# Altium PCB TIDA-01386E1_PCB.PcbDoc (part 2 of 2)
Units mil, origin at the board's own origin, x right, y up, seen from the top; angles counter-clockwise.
Board outline 3000 x 700 mil, 4 copper layers (Top Layer, Signal Layer 1, Signal Layer 2, Bottom Layer), stack 90.316 mil thick; 67 components, 41 nets, 217 pads, 102 vias.
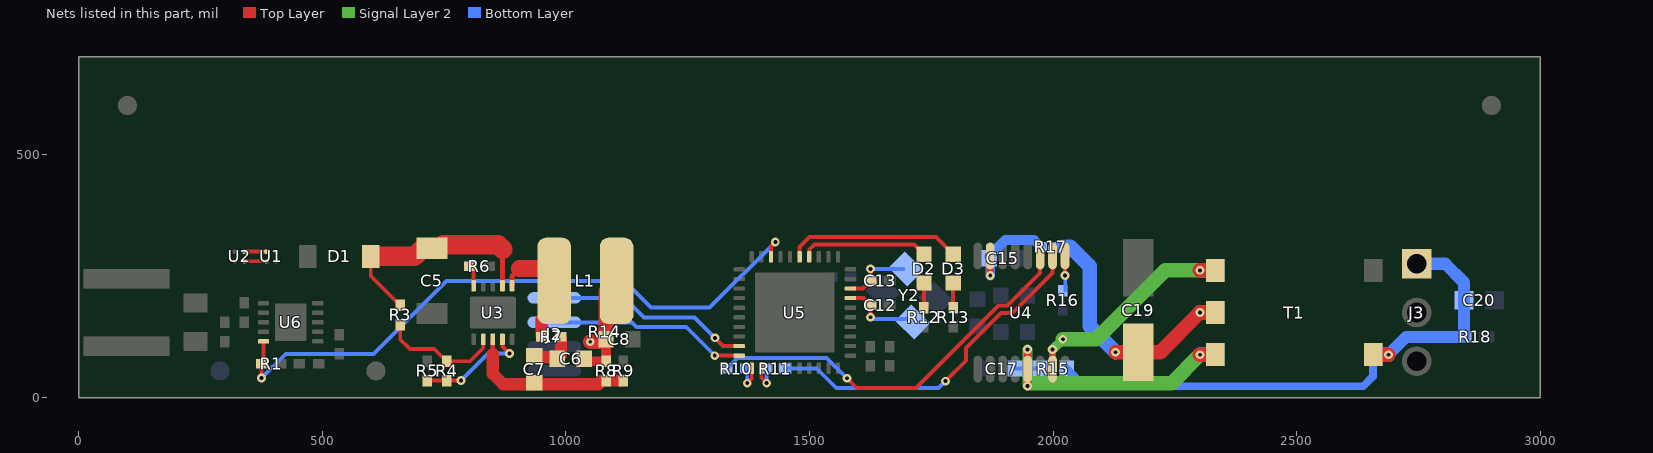
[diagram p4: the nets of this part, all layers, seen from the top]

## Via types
v1: diameter 18, hole 8, Top Layer to Bottom Layer, tented both sides, 79 vias
v2: diameter 19.68, hole 7.87, Top Layer to Bottom Layer, 16 vias
v3: diameter 19.68, hole 7.87, Top Layer to Bottom Layer, tented bottom, 4 vias
v4: diameter 56, hole 42, Top Layer to Bottom Layer, 3 vias

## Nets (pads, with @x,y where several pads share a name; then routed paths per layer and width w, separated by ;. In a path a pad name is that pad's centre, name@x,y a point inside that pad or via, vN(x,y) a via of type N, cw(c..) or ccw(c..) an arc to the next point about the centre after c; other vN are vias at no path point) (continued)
NetC5_1: C5.1 D1.1 R3.2 U3.2 | length 472.1
  Top Layer w8: D1.1@599.47,290 599.47,250.22 R3.2@660,189.69 ; U3.2@869.69,230.12 U3.2@870,230.43
  Top Layer w9.8: U3.2@870,230.43 870,295
  Top Layer w40: D1.1@602,290 689,290 705.93,306.93 C5.1@725,306.93 740.93,306.93 748,314 861,314 870,305
NetC6_2: C6.2 C7.1 R7.2 | length 93.1
  Top Layer w25: C7.1@935.44,83 979.44,83 C6.2@982.44,80 990,87.56 R7.2@990,121.68
NetC7_2: C7.2 R8.1 R9.2 U3.8 | length 347.2
  Top Layer w9.8: 850,90 U3.8@850,119.88
  Top Layer w25: 850,90 850,49.25 871.56,27.69 1066.69,27.69 1074.32,35.32 R8.1@1082.5,35.32 R9.2@1114.5,35.31
NetC12_1: C12.1 U5.37 Y2.1 | length 157.5
  Top Layer w8: U5.37@1584.17,204.53 1610.79,204.53 C12.1@1625.32,190 v1(1625.32,165.32)
  Bottom Layer w8: v1(1625.32,165.32) 1628.63,162 1700.67,162 Y2.1@1706.96,155.71
NetC13_1: C13.1 U5.38 Y2.3 | length 140.5
  Top Layer w8: U5.38@1584.17,224.21 1609.53,224.21 C13.1@1625.32,240 v1(1625.32,264.68)
  Bottom Layer w8: v1(1625.32,264.68) 1626,264 1692.75,264 Y2.3@1693.04,264.29
NetC17_2: C17.2 R15.2 | length 49.9
  Bottom Layer w8: C17.2@1922.56,60 R15.2@1972.44,60
NetC19_1: C19.1 pad.3@2333.01,175 R17.1 T1.2 | length 542.3
  Top Layer w30: v1(2128.39,93.39) C19.1@2175,93.39 2220,93.39 v1(2301.61,175) T1.2@2333.11,175
  Bottom Layer w30: R17.1@2018,310 2035,310 2075,270 2075,146.77 v1(2128.39,93.39) ; v1(2301.61,175) pad.3@2333.11,175
NetD2_1: D2.1 U5.4 | length 263.6
  Top Layer w8: U5.4@1499.53,289.17 1499.53,304.53 1510,315 1714.53,315 D2.1@1735,294.53
NetD2_2: D2.2 R12.1 | length 40.8
  Top Layer w8: R12.1@1735,194.68 D2.2@1735,235.47
NetD3_1: D3.1 U5.5 | length 358.9
  Top Layer w8: U5.5@1479.84,289.17 1479.84,309.84 1500,330 1759.53,330 D3.1@1795,294.53
NetD3_2: D3.2 R13.1 | length 40.8
  Top Layer w8: R13.1@1795,194.68 D3.2@1795,235.47
NetL1_1: L1.1 R7.1 U3.1 | length 245.4
  Top Layer w9.8: U3.1@889.37,230.12 889.37,249.37 905,265
  Top Layer w25: R7.1@950.32,128 950.32,160.32 976.02,186.02 L1.1@976.02,240
  Top Layer w35: 905,265 951.02,265 L1.1@976.02,240
NetR3_1: R3.1 R4.2 U3.7 | length 248.2
  Top Layer w8: R3.1@660,150.32 660,120 680,100 729.69,100 754.69,75 803,75 830.31,102.31 U3.7@830.31,119.88
NetR4_1: R4.1 R5.2 U3.9 | length 226.9
  Top Layer w8: R5.2@715,35.31 R4.1@755,35.32 v1(784.68,35.31) ; U3.9@869.68,119.88 869.68,105.32 v1(884,91)
  Bottom Layer w8: v1(784.68,35.31) 840.37,91 v1(884,91)
NetR6_2: R6.2 U3.5 | length 43.1
  Top Layer w8: R6.2@802.81,270 810.63,262.18 U3.5@810.63,230.12
NetR10_2: R10.2 U5.21 | length 65.7
  Top Layer w8: v1(1372.2,30) 1381.42,39.21 U5.21@1381.42,60.83
  Bottom Layer w8: R10.2@1369.69,60 1372.2,57.48 v1(1372.2,30)
NetR11_2: R11.2 U5.22 | length 66.2
  Top Layer w8: U5.22@1401.1,60.83 1401.1,41.1 v1(1412.2,30)
  Bottom Layer w8: R11.2@1410.31,60 1412.2,58.11 v1(1412.2,30)
NetR16_2: R16.2 U4.9 | length 71.6
  Top Layer w8: v1(2024.57,251.14) U4.9@2024.57,291.14
  Bottom Layer w8: v1(2024.57,251.14) 2025,250.71 R16.2@2025,219.69
NetU1_B1: U1.B1 U2.B2 | length 45.3
  Top Layer w8: U2.B2@339.84,299.84 U1.B1@385.16,299.84
NetU1_B2: U1.B2 U2.B1 | length 45.3
  Top Layer w8: U2.B1@339.84,280.16 U1.B2@385.16,280.16
OUTA: pad.3@2333.01,88.39 T1.3 U4.5 | length 595.1
  Top Layer w15: v1@1947.8,23.86 U4.5@1947.8,58.86 v1(1947.8,98.86) ; T1.3@2333.01,88.39 T1.3@2333.11,88.39
  Top Layer w30: v1(2301.61,88.39) T1.3@2333.01,88.39
  Signal Layer 2 w20: v1@1947.8,25 v1(1947.8,98.86) ; v1@1948.56,25.03 1964,25.03
  Signal Layer 2 w30: 1958,30 2243.23,30 v1(2301.61,88.39)
  Bottom Layer w30: v1(2301.61,88.39) pad.3@2333.01,88.39 pad.3@2333.11,88.39
  other v1: 1947.8,24.06
OUTB: pad.3@2333.01,261.61 T1.1 U4.7 | length 473
  Top Layer w15: U4.7@1998.98,58.86 v1(1998.98,98.86)
  Top Layer w30: v1(2301.61,261.61) T1.1@2333.11,261.61
  Signal Layer 2 w20: v1(1998.98,98.86) v1(2020.12,120)
  Signal Layer 2 w30: v1(2020.12,120) 2088.5,120 2230.11,261.61 v1(2301.61,261.61)
  Bottom Layer w30: v1(2301.61,261.61) pad.3@2333.11,261.61
RTRN: C20.1 J3.1 pad.3@2656.99,88.39 R15.1 R18.2 T1.4 | length 1160.9
  Top Layer w30: T1.4@2656.89,88.39 v1(2688.39,88.39)
  Bottom Layer w8: R15.1@2027.56,65 R15.1@2030.06,62.5
  Bottom Layer w15: pad.3@2648.39,88.39 pad.3@2650,90 ; C20.1@2843.38,199.87 C20.1@2843.5,200
  Bottom Layer w16: R15.1@2027.56,60 2064.06,23.5 2636.5,23.5 2656.89,43.89 pad.3@2656.89,88.39
  Bottom Layer w25: v1(2688.39,88.39) 2725,125 R18.2@2843.38,125 C20.1@2843.38,199.87 ; J3.1@2746.46,275 2805,275 2843.5,236.5 C20.1@2843.5,200
  Bottom Layer w30: pad.3@2656.89,88.39 v1(2688.39,88.39)
RXD_460: R10.1 U4.11 | length 810.5
  Top Layer w8: v1(1577,40) 1597,20 1719,20 1888.33,189.33 1906.33,189.33 1973.39,256.39 U4.11@1973.39,291.14
  Bottom Layer w8: R10.1@1330.32,60 1352.32,82 1535,82 v1(1577,40)
TCK: J2.4 U5.19 | length 420.4
  Top Layer w8: v1(1306,123) 1322.9,106.1 U5.19@1355.83,106.1
  Bottom Layer w8: J2.4@976.42,205 1120,205 1160,165 1264,165 v1(1306,123)
TDIO: J2.3 R14.1 U5.20 | length 412.8
  Top Layer w8: v1(1305.58,86.42) U5.20@1355.83,86.42
  Bottom Layer w8: J2.3@971.42,155 971.73,154.68 R14.1@1080,154.68 1135.32,154.68 1145,145 1247,145 v1(1305.58,86.42)
TXD_460: R11.1 U4.10 | length 714
  Top Layer w8: v1(1779,34) 1821,76 1821,102 1893,174 1917,174 1998.98,255.98 U4.10@1998.98,291.14
  Bottom Layer w8: R11.1@1449.68,60 1515,60 1555,20 1765,20 v1(1779,34)
VPWR: C6.1 C8.1 C15.1 L1.2 R8.2 R17.2 U4.15 | length 503.5
  Top Layer w8: U4.15@1871.02,291.14 U4.15@1871.02,311.02
  Top Layer w15: v1(1871.02,251.14) U4.15@1871.02,291.14
  Top Layer w20: C6.1@1037.56,80 1042.87,74.69 R8.2@1082.5,74.69 1082.5,119.94 C8.1@1082.44,120
  Top Layer w30: v1(1050,115) 1077.44,115 C8.1@1082.44,120 1082.44,218.46 L1.2@1103.98,240 L1.2@1118.98,255
  Bottom Layer w15: C15.1@1869.06,291.14 C15.1@1871.02,289.17
  Bottom Layer w20: C15.1@1869.06,291.14 1901.91,324 1961.31,324 R17.2@1975.31,310 ; v1(1871.02,251.14) C15.1@1871.02,289.17
WAKE: R1.1 U5.8 U6.10 | length 1327.7
  Top Layer w8: v1(375.32,40.32) R1.1@375.32,70 379.39,74.07 U6.10@379.39,115.63 ; U5.8@1420.79,289.17 1420.79,310.79 v1(1430,320)
  Bottom Layer w8: v1(375.32,40.32) 425,90 605,90 755,240 1120,240 1175,185 1295,185 v1(1430,320)
pads on no net: FID1.1 FID2.1 FID3.1 FID4.1 FID5.1 FID6.1 J1.2 U3.4 U3.6 U3.11@789.76,165.16 U3.11@789.76,184.84 U3.11@825.2,175 U3.11@874.8,175 U3.11@910.24,165.16 U3.11@910.24,184.84 U4.8 U4.12 U4.13 U5.1 U5.2 U5.3 U5.6 U5.7 U5.10 U5.11 U5.12 U5.13 U5.14 U5.16 U5.23 U5.24 U5.25 U5.26 U5.27 U5.28 U5.29 U5.30 U5.33 U5.34 U5.35 U5.41@1416.06,121.06 U5.41@1416.06,175 U5.41@1416.06,228.94 U5.41@1470,121.06 U5.41@1470,175 U5.41@1470,228.94 U5.41@1523.94,121.06 U5.41@1523.94,175 U5.41@1523.94,228.94

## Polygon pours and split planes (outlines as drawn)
L- on Top Layer "TOP_LAYER_L-_P014" (solid, remove dead copper, pour order 14): 2195,205 2110,205 2110,325 2195,325
L- on Top Layer "TOP_LAYER_L-_P006" (solid, remove dead copper, pour order 6): 275,265 325,265 325,315 275,315
L+ on Top Layer "TOP_LAYER_L+_P004" (solid, remove dead copper, pour order 4): 490,265 400,265 400,315 490,315
L+ on Top Layer "Top Layer-No Net 1" (solid, remove dead copper, pour order 2): 10,127 10,50 345,50 345,127
L- on Top Layer "TOP_LAYER_L-_P018" (solid, remove dead copper, pour order 18): 765,115 685,115 685,195 765,195
VPWR on Top Layer "TOP_LAYER_VPWR_P024" (solid, remove dead copper, pour order 24): 1095,60 1095,135 1020,135 1020,60
L- on Signal Layer 1 "SIGNAL_LAYER_1_L-_P008" (solid, remove dead copper, pour order 8): 192.36,10 2980,10 2980,335 192.36,335
3V3 on Signal Layer 2 "SIGNAL_LAYER_2_3V3_P012" (solid, remove dead copper, pour order 12): 320,10 1760,10 1760,160 1175,160 1095,80 1012.8,80 1012.8,340 500,340 500,220 420,220 320,120
L+ on Signal Layer 2 "SIGNAL_LAYER_2_L+_P010" (solid, remove dead copper, pour order 10): 10,10 10,340 480,340 480,240 410,240 300,130 300,10
VPWR on Signal Layer 2 "SIGNAL_LAYER_2_VPWR_P022" (solid, remove dead copper, pour order 22): 1030,100 1100,100 1175,175 1962.5,175 1962.5,340 1030,340
L- on Bottom Layer "Top Layer-No Net 1" (solid, remove dead copper, pour order 20): 0,335 0,215 305,215 305,335
NetC1_2 on Bottom Layer "BOTTOM_LAYER_NETC1_2_P026" (solid, remove dead copper, pour order 26): 15,85 210,85 220,85 285,150 285,170 15,170

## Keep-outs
Keep-Out Layer:
  lines w15: 0,350 3000,350
  text ".Layer_Name" at 577,-858.49 h60

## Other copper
Top Layer:
  text ".Layer_Name" at 577,-858.49 h60
Signal Layer 1:
  text ".Layer_Name" at 577,-858.49 h60
Signal Layer 2:
  text ".Layer_Name" at 577,-858.49 h60
Bottom Layer:
  text ".Layer_Name" at 577,-858.49 h60

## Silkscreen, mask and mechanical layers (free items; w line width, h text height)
Top Overlay:
  region: 2120,495 1820,495 1820,395 2120,395
  lines w7.87: 5,350 2995,350
  text "'.PRJ_Number'.PCB_Rev-" at 1130,410 h108.27
  text "+" at 2815,255 h72.83
  text "-" at 2820,155 h72.83
  text "-" at 2820,60 h72.83
  text ".Layer_Name" at 577,-858.49 h60
Bottom Overlay:
  lines w7.87: 5,350 2995,350
  text ".Layer_Name" at 577,-858.49 h60
Top Paste:
  text ".Layer_Name" at 577,-858.49 h60
Bottom Paste:
  text ".Layer_Name" at 577,-858.49 h60
Top Solder:
  text ".Layer_Name" at 577,-858.49 h60
  text ".Layer_Name" at 577,-858.49 h60
Bottom Solder:
  text ".Layer_Name" at 577,-858.49 h60
Drill Guide:
  text ".Layer_Name" at 577,-858.49 h60
M1 Board Outline:
  lines w7: 2360,40 2360,310 2630,310 2630,40 2360,40
  lines w10: 0,0 3000,0 3000,350 3000,700 0,700 0,350 0,0
  text ".Layer_Name" at 577,-858.49 h60
M2 Board Dimensions:
  rectangle: 125,-400 500,-275
  rectangle: 0,-275 125,-150
  lines w7: 0,-275 1000,-275 ; 125,-400 125,-150 ; 250,-400 250,-150 ; 500,-400 500,-150 ; 750,-400 750,-150 ; 0,-400 0,-150 1000,-150 1000,-400 0,-400
  text ".Layer_Name" at 577,-858.49 h60
M3 3D STEP Top:
  text ".Layer_Name" at 577,-858.49 h60
M4 3D STEP Bottom:
  text ".Layer_Name" at 577,-858.49 h60
M5 Assembly Top:
  lines w10: -292,-930.17 6308,-930.17 ; -292,-726.83 6310,-726.83 ; -292,-523.5 -292,-1133.5 3713,-1133.5 6310,-1133.5 6310,-523.5 -291.5,-523.5 -291.5,-1133.5 1284,-1133.5 ; 2173,-1133.5 2173,-523.5 ; 3440,-726.83 3440,-523.5 ; 4280,-726.83 4280,-523.5 ; 4902,-1140 4902,-937.17
  text "COMPONENTS MARKED 'DNP' SHOULD NOT BE POPULATED." at 1153.5,-318.5 h60
  text "ASSEMBLY VARIANT:" at 1153,-434 h60
  text ".VariantName" at 2189,-434 h60
  text "PCB VIEWED FROM TOP SIDE" at -228.5,-655.67 h60
  text "BOARD #:" at 2248,-655.67 h60
  text ".PRJ_Number" at 2793.5,-655.67 h60
  text "REV:" at 3638,-655.67 h60
  text ".PCB_Rev" at 3929.5,-655.67 h60
  text "SVN REV:" at 4476,-655.67 h60
  text ".VersionControl_RevNumber" at 4982,-655.67 h60
  text "TID #:" at 2248,-859 h60
  text ".TID" at 2793.5,-859 h60
  text "PLOT NAME =" at -228.5,-1064.34 h60
  text ".plot_File_Name" at 577,-1064.34 h60
  text "GENERATED    :" at 2250,-1064.34 h60
  text ".Print_Date" at 3119.5,-1064.34 h60
  text ".Print_Time" at 3848.5,-1064.34 h60
  text "TEXAS INSTRUMENTS" at 5113,-1064.34 h60
M6 Assembly Bottom:
  lines w10: -292.5,-727.33 6309.5,-727.33 ; -290.5,-930.67 6309.5,-930.67 ; 1115.5,-1140.5 1115.5,-937.67 ; 1737.5,-727.33 1737.5,-524 ; 2577.5,-727.33 2577.5,-524 ; 3844.5,-1134 3844.5,-524 ; 4733.5,-1134 6309,-1134 6309,-524 -292.5,-524 -292.5,-1134 2304.5,-1134 6309.5,-1134 6309.5,-524
  text "COMPONENTS MARKED 'DNP' SHOULD NOT BE POPULATED." at 6102,-318 h60
  text ".VariantName" at 5058,-434 h60
  text "ASSEMBLY VARIANT:" at 6097,-434 h60
  text ".VersionControl_RevNumber" at 1035.5,-656.17 h60
  text "SVN REV:" at 1541.5,-656.17 h60
  text ".PCB_Rev" at 2088,-656.17 h60
  text "REV:" at 2379.5,-656.17 h60
  text ".PRJ_Number" at 3224,-656.17 h60
  text "BOARD #:" at 3769.5,-656.17 h60
  text "PCB VIEWED FROM BOTTOM SIDE" at 6246,-656.17 h60
  text ".TID" at 3224,-859.5 h60
  text "TID #:" at 3769.5,-859.5 h60
  text "TEXAS INSTRUMENTS" at 904.5,-1064.84 h60
  text ".Print_Time" at 2169,-1064.84 h60
  text ".Print_Date" at 2898,-1064.84 h60
  text "GENERATED    :" at 3767.5,-1064.84 h60
  text ".plot_File_Name" at 5440.5,-1064.84 h60
  text "PLOT NAME =" at 6246,-1064.84 h60
M9 Title Sheet:
  drawing of 56 lines, arcs and shapes, not listed
  text "1" at 739.84,8036.5 h70
  text "2" at 3235.5,8036.5 h70
  text "3" at 5724.84,8036.5 h70
  text "4" at 8231.51,8036.5 h70
  text "5" at 10730.5,8036.5 h70
  text "6" at 13235.5,8036.5 h70
  text "A" at -416.5,6893.5 h70
  text "A" at 14383.5,6893.5 h70
  text "B" at -416.5,4513.5 h70
  text "B" at 14383.5,4513.5 h70
  text "C" at -416.5,2138.5 h70
  text "C" at 14383.5,2138.5 h70
  text "PROJECT TITLE:" at 11343.5,277.5 h45
  text ".PRJ_Title" at 11393.5,144.17 h70
  text "DESIGNED FOR:" at 11343.5,-23.5 h45
  text ".PRJ_Customer" at 11393.5,-163.5 h70
  text "D" at -416.5,-231.5 h70
  text "D" at 14383.5,-231.5 h70
  text "FILE NAME:" at 11343.5,-323.5 h45
  text ".PCB_File_Name_No_Path" at 11393.5,-443.5 h70
  text "Texas Instruments (TI) and/or its licensors do not warrant the accuracy or completeness of this specification" at 6374,-605.34 h45
  text "ENGINEER:" at 11343.5,-613.5 h45
  text "LAYOUT BY:" at 12848.5,-613.5 h45
  text "or any information contained therein. TI and/or its licensors do not warrant that this design will meet" at 6329.01,-718 h45
  text ".PRJ_Engineer" at 11393.5,-768.49 h70
  text ".PCB_Layout" at 12899,-768.49 h70
  text "the specifications, will be suitable for your application or fit for any particular purpose, or will operate in" at 6329.01,-830.67 h45
  text ".Layer_Name" at 577,-858.49 h60
  text "ALTIUM DESIGNER VERSION:" at 12848.5,-923.5 h45
  text "an implementation. TI and/or its licensors do not warrant that the design is production worthy. You should" at 6329.01,-943.33 h45
  text "completely validate and test your design implementation to confirm the system functionality for your application." at 6374,-1056 h45
  text ".print_Scale" at 11393.5,-1056.83 h70
  text ".Application_BuildNumber" at 12899,-1056.83 h70
  text "1" at 739.84,-1263.5 h70
  text "2" at 3235.5,-1263.5 h70
  text "3" at 5724.84,-1263.5 h70
  text "4" at 8231.51,-1263.5 h70
  text "5" at 10730.5,-1263.5 h70
  text "6" at 13235.5,-1263.5 h70
M10 Fab Notes:
  drawing of 173 lines, arcs and shapes, not listed
  text "DESIGN INFORMATION" at 12378.02,6201 h60
  text "MIN. TRACK WIDTH:" at 11733.46,6021 h60
  text "6" at 12829.7,6021 h60
  text "MIL" at 12984.46,6021 h60
  text "MIN. CLEARANCE:" at 11733.46,5889 h60
  text "0.15" at 12769.7,5889 h60
  text "mm" at 12984.46,5889 h60
  text "MIN. VIA PAD SIZE:" at 11733.46,5757 h60
  text "18" at 12799.71,5757 h60
  text "MIL" at 12984.46,5757 h60
  text "0.05mm (2MIL)" at 12428.46,5615.29 h60
  text "MINIMUM ANNULAR RING" at 11404.23,5611 h60
  text "EXTERNAL" at 13136.46,5611 h60
  text "PER" at 11604.23,5493 h60
  text "IPC-D-275 CLASS 2 LEVEL C" at 11824.23,5493 h60
  text "MIL, HOLES" at 13312.46,5380.71 h60
  text "+/-" at 12920,5380 h60
  text "+/-" at 13774,5380 h60
  text "REGISTRATION TOLERANCES:" at 11404.23,5375 h60
  text "METAL" at 12604,5375 h60
  text "5" at 13180.2,5375 h60
  text "3" at 14013.2,5375 h60
  text "MIL" at 14129.46,5375 h60
  text "+/-" at 13774,5262 h60
  text "HOLE SIZE TOLERANCE (UNLESS OTHERWISE SPECIFIED):" at 11404.23,5257 h60
  text "3" at 14013.2,5257 h60
  text "MIL" at 14129.46,5257 h60
  text "MATERIAL:" at 11329.46,5047.54 h60
  text "FR-4 High Tg" at 12315.9,4907.21 h60
  text "FR-408" at 11750.46,4898.64 h60
  text "OTHER" at 13238.46,4898.64 h60
  text "X" at 12161,4895 h60
  text "62 MIL (1.6mm) +/-10%" at 12070.56,4735.92 h60
  text "THICKNESS:" at 11404.23,4731.64 h60
  text "X" at 11942.4,4731.64 h60
  text "OTHER" at 13355.46,4731.64 h60
  text "TOLERANCE:" at 11404.23,4573.64 h60
  text "X" at 12243.53,4573.64 h60
  text "ANSI IPC-6012 TYPE 3 CLASS 2" at 12430.48,4573.64 h60
  text "OTHER +/-" at 12430.46,4417.64 h60
  text "BOW & TWIST:" at 11404.23,4260.64 h60
  text "X" at 12243.53,4260.64 h60
  text "ANSI IPC-6012 TYPE 3 CLASS 2" at 12430.48,4260.64 h60
  text "OTHER +/-" at 12430.46,4102.13 h60
  text "DRILLING:" at 11329.46,3963.64 h60
  text "REFERENCE:" at 11404.23,3846.64 h60
  text "X" at 12052.46,3846.64 h60
  text "AS SHOWN" at 12239.46,3846.64 h60
  text "X" at 12953.46,3846.64 h60
  text "NC_DRILL FILES" at 13090.46,3846.64 h60
  text "PTH COPPER THICKNESS:" at 11404.23,3688.64 h60
  text "X" at 12534.46,3688.64 h60
  text "20-30 um" at 12671.46,3688.64 h60
  text "OTHER" at 13388.46,3688.64 h60
  text "BOARD FINISH:" at 11329.46,3529.64 h60
  text "SILKSCREEN:" at 11484.68,3411.64 h60
  text "X" at 12433.46,3411.64 h60
  text "TOP" at 12559.46,3411.64 h60
  text "X" at 12943.46,3411.64 h60
  text "BOTTOM" at 13070.46,3411.64 h60
  text "SILKSCREEN COLOR:" at 11484.68,3244.64 h60
  text "X" at 12432.42,3244.64 h60
  text "WHITE" at 12559.46,3244.64 h60
  text "OTHER" at 13070.46,3244.64 h60
  text "X" at 12563.42,3085.44 h60
  text "GREEN" at 12690.46,3085.44 h60
  text "OTHER" at 13308.46,3085.44 h60
  text "SOLDER RESIST COLOR:" at 11484.68,3074.64 h60
  text "X" at 12563.42,2915.44 h60
  text "MATTE" at 12690.46,2915.44 h60
  text "SEMI-GLOSS" at 13308,2914.8 h60
  text "IMMERSION GOLD (ENIG)" at 12390.46,2726.92 h60
  text "ENEPIG" at 13728,2723.64 h60
  text "SURFACE FINISH:" at 11329.46,2722.64 h60
  text "X" at 12203.51,2722.64 h60
  text "IMM. TIN/SILVER OR EQUIV" at 11659,2565.64 h60
  text "OTHER" at 13090.46,2565.64 h60
  text "ARRAY/PANEL:" at 11329.46,2386.64 h60
  text "CUT AND TRIM PER M1 BOARD OUTLINE" at 12390.46,2382.35 h60
  text "N.C. ROUTE" at 12390.46,2230.64 h60
  text "X" at 13069.46,2230.64 h60
  text "V. SCORE" at 13256.46,2230.64 h60
  text "CERTIFICATION:" at 11329.46,2093.64 h60
  text "MATERIALS AND WORKMANSHIP FOR ALL PCBS" at 12054.46,2093.64 h60
  text "TO MEET OR EXCEED THE REQUIREMENTS OF:" at 12054.46,1995.64 h60
  text "X" at 11680.96,1859.13 h60
  text "ANSI IPC-A-600F CLASS ->" at 11819.96,1859.13 h60
  text "X" at 13459.02,1859.13 h60
  text "2" at 13577.96,1859.14 h60
  text "1" at 13262.96,1857.64 h60
  text "3" at 13931.96,1857.64 h60
  text "X" at 12495.02,1699.64 h60
  text "RoHS" at 12631.96,1699.64 h60
  text "OTHER" at 13276.36,1699.64 h60
  text "PER ORDER" at 13673.42,1699.64 h60
  text "ALL BOARDS MUST MEET OR EXCEED UL94-V0 REQUIREMENTS." at 11357,1534 h60
  text "PCB MUST BEAR THE UL94V-0 UL REGISTERED MATERIAL ID NUMBER" at 11357,1414 h60
  text "ADDITIONAL REQUIREMENTS:" at 11329.46,1240.64 h60
  text "MICROSECTION:" at 11404.23,1125.64 h60
  text "YES" at 12309.96,1125.64 h60
  text "REQUIRED" at 13171.46,969.49 h60
  text "BARE BOARD ELEC. TEST:" at 11404.23,966.64 h60
  text "NONE" at 12709.96,966.64 h60
  text "X" at 13044.46,966.64 h60
  text "PER ORDER" at 13763.46,966.64 h60
  text ".Layer_Name" at 577,-858.49 h60
M11 Gerber Information:
  lines w10: -292,-930.17 6308,-930.17 ; -292,-726.83 6310,-726.83 ; -292,-523.5 -292,-1133.5 3713,-1133.5 6310,-1133.5 6310,-523.5 -291.5,-523.5 -291.5,-1133.5 1284,-1133.5 ; 2173,-1133.5 2173,-523.5 ; 3440,-726.83 3440,-523.5 ; 4280,-726.83 4280,-523.5 ; 4902,-1140 4902,-937.17
  text "ALL ARTWORK VIEWED FROM TOP SIDE" at -228.5,-655.67 h60
  text "BOARD #:" at 2248,-655.67 h60
  text ".PRJ_Number" at 2793.5,-655.67 h60
  text "REV:" at 3638,-655.67 h60
  text ".PCB_Rev" at 3929.5,-655.67 h60
  text "SVN REV:" at 4476,-655.67 h60
  text ".VersionControl_RevNumber" at 4982,-655.67 h60
  text "LAYER NAME =" at -228.5,-858.49 h60
  text "TID #:" at 2248,-859 h60
  text ".TID" at 2793.5,-859 h60
  text "PLOT NAME =" at -228.5,-1064.34 h60
  text ".plot_File_Name" at 577,-1064.34 h60
  text "GENERATED    :" at 2250,-1064.34 h60
  text ".Print_Date" at 3119.5,-1064.34 h60
  text ".Print_Time" at 3848.5,-1064.34 h60
  text "TEXAS INSTRUMENTS" at 5113,-1064.34 h60
M12 Stackup:
  drawing of 295 lines, arcs and shapes, not listed
  text "Layer" at 9797.84,7830 h60
  text "Name" at 10207.76,7830 h60
  text "Material" at 11147.5,7830 h60
  text "Thickness" at 12007.26,7830 h60
  text "Constant" at 12657.1,7830 h60
  text "Board Layer Stack" at 13226.96,7830 h60
  text "1" at 9797.84,7710 h60
  text "Top Overlay" at 10207.76,7710 h60
  text "2" at 9797.84,7590 h60
  text "Top Solder" at 10207.76,7590 h60
  text "Solder Resist" at 11147.5,7590 h60
  text "0.40mil" at 12007.26,7590 h60
  text "3.5" at 12657.1,7590 h60
  text "3" at 9797.84,7470 h60
  text "Top Layer" at 10207.76,7470 h60
  text "Copper" at 11147.5,7470 h60
  text "1.46mil" at 12007.26,7470 h60
  text "4" at 9797.84,7350 h60
  text "Dielectric1" at 10207.76,7350 h60
  text "FR-4" at 11147.5,7350 h60
  text "20.08mil" at 12007.26,7350 h60
  text "4.8" at 12657.1,7350 h60
  text "5" at 9797.84,7230 h60
  text "Signal Layer 1" at 10207.76,7230 h60
  text "Copper" at 11147.5,7230 h60
  text "1.38mil" at 12007.26,7230 h60
  text "6" at 9797.84,7110 h60
  text "Dielectric 2" at 10207.76,7110 h60
  text "FR-4" at 11147.5,7110 h60
  text "44.49mil" at 12007.26,7110 h60
  text "4.8" at 12657.1,7110 h60
  text "7" at 9797.84,6990 h60
  text "Signal Layer 2" at 10207.76,6990 h60
  text "Copper" at 11147.5,6990 h60
  text "1.38mil" at 12007.26,6990 h60
  text "8" at 9797.84,6870 h60
  text "Dielectric 3" at 10207.76,6870 h60
  text "FR-4" at 11147.5,6870 h60
  text "20.08mil" at 12007.26,6870 h60
  text "4.8" at 12657.1,6870 h60
  text "9" at 9797.84,6750 h60
  text "Bottom Layer" at 10207.76,6750 h60
  text "Copper" at 11147.5,6750 h60
  text "1.46mil" at 12007.26,6750 h60
  text "10" at 9797.84,6630 h60
  text "Bottom Solder" at 10207.76,6630 h60
  text "Solder Resist" at 11147.5,6630 h60
  text "0.40mil" at 12007.26,6630 h60
  text "3.5" at 12657.1,6630 h60
  text "11" at 9797.84,6510 h60
  text "Bottom Overlay" at 10207.76,6510 h60
  text ".Layer_Name" at 577,-858.49 h60
M13 Component Bodies Top:
  text ".Layer_Name" at 577,-858.49 h60
M14 Component Bodies Bottom:
  text ".Layer_Name" at 577,-858.49 h60
M15 Courtyards Top:
  text ".Layer_Name" at 577,-858.49 h60
M16 Courtyards Bottom:
  text ".Layer_Name" at 577,-858.49 h60
Drill Drawing:
  circle w10: c5363.72,3017.64 r27.63
  lines w10: 5336.09,2920.95 5391.34,2920.95 5363.72,2865.7 5336.09,2920.95 ; 5336.09,3114.34 5336.09,3128.15 5349.9,3141.96 5336.09,3155.78 5336.09,3169.59 5349.9,3169.59 5363.72,3155.78 5377.53,3169.59 5391.34,3169.59 5391.34,3155.78 5377.53,3141.96 5391.34,3128.15 5391.34,3114.34 5377.53,3114.34 5363.72,3128.15 5349.9,3114.34 5336.09,3114.34 ; 5336.09,3238.66 5391.34,3238.66 5391.34,3293.91 5336.09,3293.91 5336.09,3238.66
  lines w12: 5286,2828.4 8517.49,2828.4 ; 5286,3325.68 8517.49,3325.68 ; 5623.86,2704.08 5623.86,3450 ; 5955.86,2704.08 5955.86,3450 ; 6592.43,2704.08 6592.43,3450 ; 6851.57,2704.08 6851.57,3450 ; 7226.72,2704.08 7226.72,3450 ; 7951.05,2704.08 7951.05,3450 ; 5286,2704.08 8517.49,2704.08 8517.49,3450 5286,3450 5286,2704.08
  text "Symbol" at 5360.59,3362.98 h72
  text "Quantity" at 5661.16,3362.98 h72
  text "Finished Hole Size" at 5993.16,3362.98 h72
  text "Plated" at 6629.72,3362.98 h72
  text "Hole Type" at 6888.86,3362.98 h72
  text "Drill Layer Pair" at 7264.02,3362.98 h72
  text "Hole Tolerance" at 7988.35,3362.98 h72
  text "20" at 5661.16,3238.66 h60
  text "7.87mil (0.200mm)" at 5993.16,3238.66 h60
  text "PTH" at 6629.72,3238.66 h60
  text "Round" at 6888.86,3238.66 h60
  text "Top Layer - Bottom Layer" at 7264.02,3238.66 h60
  text "79" at 5661.16,3114.34 h60
  text "8.00mil (0.203mm)" at 5993.16,3114.34 h60
  text "PTH" at 6629.72,3114.34 h60
  text "Round" at 6888.86,3114.34 h60
  text "Top Layer - Bottom Layer" at 7264.02,3114.34 h60
  text "3" at 5661.16,2990.02 h60
  text "40.16mil (1.020mm)" at 5993.16,2990.02 h60
  text "PTH" at 6629.72,2990.02 h60
  text "Round" at 6888.86,2990.02 h60
  text "Top Layer - Bottom Layer" at 7264.02,2990.02 h60
  text "3" at 5661.16,2865.7 h60
  text "42.00mil (1.067mm)" at 5993.16,2865.7 h60
  text "PTH" at 6629.72,2865.7 h60
  text "Round" at 6888.86,2865.7 h60
  text "Top Layer - Bottom Layer" at 7264.02,2865.7 h60
  text "105 Total" at 5661.16,2741.38 h60
  text ".Layer_Name" at 577,-858.49 h60
M17 Embedded Cavity:
  text ".Layer_Name" at 577,-858.49 h60
M18 Embedded Assembly:
  text ".Layer_Name" at 577,-858.49 h60
M19 Embedded Keepout:
  text ".Layer_Name" at 577,-858.49 h60
M20 Panel:
  lines w10: 0,350 3000,350
  text ".Layer_Name" at 577,-858.49 h60

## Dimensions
0,-400 to 1000,-400 on M2 Board Dimensions
0,0 to 3000,0 on M2 Board Dimensions
0,0 to 0,350 on M2 Board Dimensions
0,350 to 0,700 on M2 Board Dimensions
